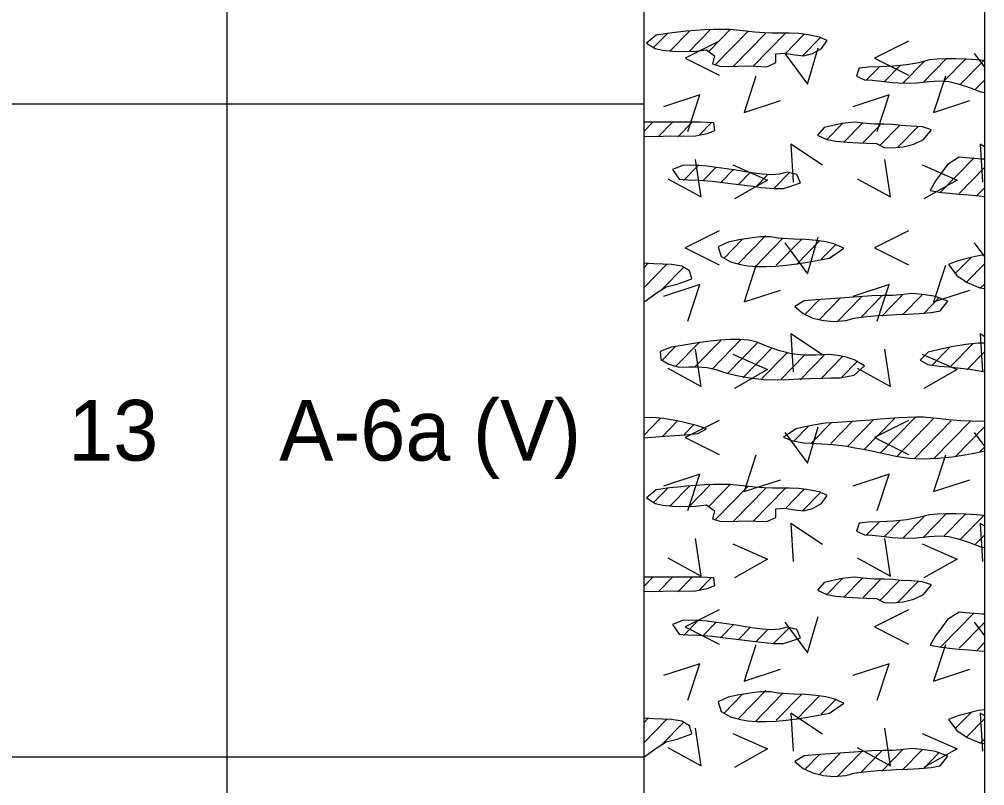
# Model space of a CAD drawing. Extents: x 0 to 0.83, y -0.65 to 1.27.
# Drawn here: x 0.7272 to 0.8333, y 0.5708 to 0.655 of the extents above; entities that cross this region are included whole.
import ezdxf

# ---------------------------------------------------------------- set-up
doc = ezdxf.new("R2010")
doc.units = 0

msp = doc.modelspace()

# ---------------------------------------------------------------- linework, layer by layer
for points in [[(0, 0), (0.83333, 0), (0.83333, 1.275), (0, 1.275)], [(0, 0), (0.83333, 0), (0.83333, 1.275), (0, 1.275)], [(0, 0), (0.83333, 0), (0.83333, 1.275), (0, 1.275)], [(0, 0), (0.83333, 0), (0.83333, 1.275), (0, 1.275)], [(0, 0), (0.83333, 0), (0.83333, 1.275), (0, 1.275)], [(0.79708, 0.65181), (0.79794, 0.65163), (0.79904, 0.65152), (0.80028, 0.65149), (0.80156, 0.65154), (0.80274, 0.65169), (0.80361, 0.65103), (0.80338, 0.65014), (0.80422, 0.64987), (0.80517, 0.64985), (0.80613, 0.6499), (0.8072, 0.64993), (0.80818, 0.6499), (0.80939, 0.64983), (0.81037, 0.65029), (0.81038, 0.65124), (0.8113, 0.6513), (0.81244, 0.65112), (0.81346, 0.65101), (0.81438, 0.65127), (0.81539, 0.65181), (0.81601, 0.65272), (0.81517, 0.65309), (0.81374, 0.65337), (0.81285, 0.65346), (0.81187, 0.65352), (0.81, 0.65352), (0.8091, 0.65354), (0.808, 0.65362), (0.80678, 0.65377), (0.8053, 0.6539), (0.80443, 0.65392), (0.80349, 0.6539), (0.80251, 0.65386), (0.80152, 0.6538), (0.80054, 0.65372), (0.79959, 0.65363), (0.7987, 0.65353), (0.79722, 0.65331), (0.79614, 0.65243)], [(0.83241, 0.65059), (0.83129, 0.65066), (0.83017, 0.65069), (0.8291, 0.65069), (0.82811, 0.65066), (0.82728, 0.65057), (0.82608, 0.65027), (0.82476, 0.65004), (0.8233, 0.6499), (0.82183, 0.64982), (0.82051, 0.64976), (0.81951, 0.64966), (0.81922, 0.6488), (0.82013, 0.64838), (0.82097, 0.64833), (0.822, 0.64823), (0.82318, 0.6481), (0.82448, 0.64801), (0.82584, 0.64804), (0.82719, 0.6482), (0.82836, 0.64827), (0.8294, 0.64819), (0.83043, 0.64795), (0.83156, 0.64756), (0.83291, 0.64707), (0.83333, 0.647), (0.83333, 0.65052)], [(0.79583, 0.64218), (0.79676, 0.64217), (0.79792, 0.64219), (0.79882, 0.64223), (0.79992, 0.64218), (0.80151, 0.64223), (0.80282, 0.64248), (0.80367, 0.6428), (0.80354, 0.64364), (0.80216, 0.64373), (0.79583, 0.64373)], [(0.81822, 0.64153), (0.81944, 0.64147), (0.82033, 0.64143), (0.82145, 0.64137), (0.82229, 0.64095), (0.82324, 0.64091), (0.82438, 0.64101), (0.82555, 0.6413), (0.82662, 0.64181), (0.82749, 0.6429), (0.82651, 0.64321), (0.82524, 0.64331), (0.82413, 0.64337), (0.82324, 0.64348), (0.82226, 0.6435), (0.82121, 0.64352), (0.81995, 0.64361), (0.81902, 0.64373), (0.81761, 0.64359), (0.81566, 0.64314), (0.81496, 0.6423), (0.81598, 0.64182), (0.81695, 0.64164)], [(0.83305, 0.63968), (0.83171, 0.63979), (0.83054, 0.63989), (0.82925, 0.63907), (0.82857, 0.63816), (0.82792, 0.63727), (0.82735, 0.63624), (0.82858, 0.63602), (0.82945, 0.63592), (0.83045, 0.63582), (0.83155, 0.63573), (0.83272, 0.63563), (0.83333, 0.63558), (0.83333, 0.63967)], [(0.80066, 0.63738), (0.80188, 0.63737), (0.80339, 0.63724), (0.80423, 0.63714), (0.8051, 0.63703), (0.806, 0.63692), (0.80692, 0.6368), (0.80784, 0.63668), (0.80875, 0.63657), (0.81014, 0.63643), (0.81119, 0.63644), (0.81222, 0.63678), (0.81308, 0.63707), (0.81267, 0.63797), (0.8116, 0.63822), (0.81075, 0.63802), (0.80989, 0.63794), (0.80885, 0.63802), (0.80799, 0.63813), (0.80703, 0.63827), (0.806, 0.63844), (0.80492, 0.6386), (0.80384, 0.63876), (0.8028, 0.63889), (0.80182, 0.63898), (0.8002, 0.63899), (0.79901, 0.63852), (0.79974, 0.63748)], [(0.81233, 0.63087), (0.81063, 0.63099), (0.80977, 0.63112), (0.8086, 0.63113), (0.80755, 0.63099), (0.80632, 0.63079), (0.80513, 0.63054), (0.80403, 0.63002), (0.80436, 0.62896), (0.80536, 0.62839), (0.80647, 0.6281), (0.8073, 0.62795), (0.80824, 0.62787), (0.80926, 0.62786), (0.81035, 0.62791), (0.81149, 0.62801), (0.81267, 0.62816), (0.81386, 0.62834), (0.81506, 0.62856), (0.81625, 0.62879), (0.81783, 0.62987), (0.81673, 0.63037), (0.81585, 0.63057), (0.8148, 0.63073), (0.81361, 0.63083)], [(0.83265, 0.62906), (0.83136, 0.62875), (0.83028, 0.62847), (0.82934, 0.62808), (0.83026, 0.62688), (0.83142, 0.62612), (0.83279, 0.62554), (0.83333, 0.62544), (0.83333, 0.62915)], [(0.79583, 0.62396), (0.79719, 0.62495), (0.79831, 0.62565), (0.79951, 0.62592), (0.80111, 0.62653), (0.80086, 0.62741), (0.80002, 0.62789), (0.79889, 0.62808), (0.79791, 0.62811), (0.79694, 0.62817), (0.79583, 0.62825)], [(0.82537, 0.6249), (0.82408, 0.62475), (0.82319, 0.6247), (0.82214, 0.62467), (0.82091, 0.62464), (0.81947, 0.62454), (0.81792, 0.62442), (0.81632, 0.6243), (0.81475, 0.62421), (0.81348, 0.62411), (0.81247, 0.62347), (0.81337, 0.62271), (0.81444, 0.62221), (0.81561, 0.62192), (0.81675, 0.62181), (0.81807, 0.62192), (0.81896, 0.6222), (0.82003, 0.62234), (0.82157, 0.62247), (0.82253, 0.62252), (0.82362, 0.62258), (0.82483, 0.62264), (0.82618, 0.62271), (0.82745, 0.62282), (0.82842, 0.62299), (0.82927, 0.62405), (0.82791, 0.62457), (0.82679, 0.62477)], [(0.79885, 0.619), (0.79763, 0.61854), (0.79773, 0.61764), (0.79859, 0.61712), (0.7997, 0.61682), (0.80074, 0.61683), (0.80165, 0.61684), (0.80281, 0.61676), (0.80377, 0.61655), (0.80486, 0.6162), (0.80606, 0.61591), (0.80751, 0.61563), (0.80905, 0.61545), (0.81052, 0.61542), (0.81177, 0.61547), (0.81289, 0.61551), (0.81408, 0.61555), (0.81553, 0.61559), (0.81642, 0.61562), (0.81745, 0.61565), (0.81897, 0.61592), (0.82011, 0.61696), (0.81896, 0.61763), (0.8181, 0.61789), (0.81717, 0.61809), (0.81626, 0.61819), (0.81479, 0.61814), (0.81343, 0.61814), (0.8121, 0.61829), (0.8108, 0.61859), (0.80953, 0.61905), (0.8082, 0.6196), (0.80736, 0.61976), (0.8064, 0.61984), (0.80536, 0.61984), (0.80427, 0.61978), (0.80314, 0.61967), (0.80201, 0.61952), (0.8009, 0.61935), (0.79984, 0.61917)], [(0.83263, 0.61944), (0.83126, 0.6193), (0.82969, 0.61904), (0.82883, 0.61887), (0.82712, 0.61846), (0.82623, 0.61759), (0.82708, 0.61709), (0.82831, 0.61691), (0.82941, 0.61684), (0.83033, 0.61675), (0.83165, 0.61657), (0.83253, 0.61643), (0.83333, 0.61629), (0.83333, 0.61943)], [(0.79583, 0.60904), (0.79715, 0.60915), (0.79814, 0.60922), (0.79922, 0.6093), (0.80039, 0.60938), (0.80179, 0.60951), (0.80275, 0.61002), (0.80179, 0.61036), (0.80091, 0.61058), (0.80003, 0.6108), (0.79909, 0.611), (0.79803, 0.61117), (0.79677, 0.61127), (0.79583, 0.61124)], [(0.82816, 0.60679), (0.82978, 0.60696), (0.83137, 0.60721), (0.8329, 0.60752), (0.83333, 0.60763), (0.83333, 0.61087), (0.83295, 0.61084), (0.83188, 0.61086), (0.83071, 0.61091), (0.82938, 0.61101), (0.82807, 0.61118), (0.82662, 0.6113), (0.82576, 0.6113), (0.82484, 0.61128), (0.82387, 0.61123), (0.82286, 0.61116), (0.82182, 0.61108), (0.82077, 0.61099), (0.81973, 0.61091), (0.81872, 0.61084), (0.81715, 0.61074), (0.81579, 0.61065), (0.81491, 0.61051), (0.81357, 0.61024), (0.8126, 0.61003), (0.81121, 0.60911), (0.8121, 0.60875), (0.81345, 0.6085), (0.81479, 0.60841), (0.81668, 0.60831), (0.81818, 0.60811), (0.81905, 0.60796), (0.82, 0.60778), (0.82107, 0.60757), (0.82225, 0.60732), (0.82357, 0.60703), (0.82501, 0.6068), (0.82656, 0.60673)], [(0.79708, 0.60181), (0.79794, 0.60163), (0.79904, 0.60152), (0.80028, 0.60149), (0.80156, 0.60154), (0.80274, 0.60169), (0.80361, 0.60103), (0.80338, 0.60014), (0.80422, 0.59987), (0.80517, 0.59985), (0.80613, 0.5999), (0.8072, 0.59993), (0.80818, 0.5999), (0.80939, 0.59983), (0.81037, 0.60029), (0.81038, 0.60124), (0.8113, 0.6013), (0.81244, 0.60112), (0.81346, 0.60101), (0.81438, 0.60127), (0.81539, 0.60181), (0.81601, 0.60272), (0.81517, 0.60309), (0.81374, 0.60337), (0.81285, 0.60346), (0.81187, 0.60352), (0.81, 0.60352), (0.8091, 0.60354), (0.808, 0.60362), (0.80678, 0.60377), (0.8053, 0.6039), (0.80443, 0.60392), (0.80349, 0.6039), (0.80251, 0.60386), (0.80152, 0.6038), (0.80054, 0.60372), (0.79959, 0.60363), (0.7987, 0.60353), (0.79722, 0.60331), (0.79614, 0.60243)], [(0.83241, 0.60059), (0.83129, 0.60066), (0.83017, 0.60069), (0.8291, 0.60069), (0.82811, 0.60066), (0.82728, 0.60057), (0.82608, 0.60027), (0.82476, 0.60004), (0.8233, 0.5999), (0.82183, 0.59982), (0.82051, 0.59976), (0.81951, 0.59966), (0.81922, 0.5988), (0.82013, 0.59838), (0.82097, 0.59833), (0.822, 0.59823), (0.82318, 0.5981), (0.82448, 0.59801), (0.82584, 0.59804), (0.82719, 0.5982), (0.82836, 0.59827), (0.8294, 0.59819), (0.83043, 0.59795), (0.83156, 0.59756), (0.83291, 0.59707), (0.83333, 0.597), (0.83333, 0.60052)], [(0.79583, 0.59218), (0.79676, 0.59217), (0.79792, 0.59219), (0.79882, 0.59223), (0.79992, 0.59218), (0.80151, 0.59223), (0.80282, 0.59248), (0.80367, 0.5928), (0.80354, 0.59364), (0.80216, 0.59373), (0.79583, 0.59373)], [(0.81822, 0.59153), (0.81944, 0.59147), (0.82033, 0.59143), (0.82145, 0.59137), (0.82229, 0.59095), (0.82324, 0.59091), (0.82438, 0.59101), (0.82555, 0.5913), (0.82662, 0.59181), (0.82749, 0.5929), (0.82651, 0.59321), (0.82524, 0.59331), (0.82413, 0.59337), (0.82324, 0.59348), (0.82226, 0.5935), (0.82121, 0.59352), (0.81995, 0.59361), (0.81902, 0.59373), (0.81761, 0.59359), (0.81566, 0.59314), (0.81496, 0.59231), (0.81598, 0.59182), (0.81695, 0.59164)], [(0.83305, 0.58968), (0.83171, 0.58979), (0.83054, 0.58989), (0.82925, 0.58907), (0.82857, 0.58816), (0.82792, 0.58727), (0.82735, 0.58624), (0.82858, 0.58602), (0.82945, 0.58592), (0.83045, 0.58582), (0.83155, 0.58573), (0.83272, 0.58563), (0.83333, 0.58558), (0.83333, 0.58967)], [(0.80066, 0.58738), (0.80188, 0.58737), (0.80339, 0.58724), (0.80423, 0.58714), (0.8051, 0.58703), (0.806, 0.58692), (0.80692, 0.5868), (0.80784, 0.58668), (0.80875, 0.58657), (0.81014, 0.58643), (0.81119, 0.58644), (0.81222, 0.58678), (0.81308, 0.58707), (0.81267, 0.58797), (0.8116, 0.58822), (0.81075, 0.58802), (0.80989, 0.58794), (0.80885, 0.58802), (0.80799, 0.58813), (0.80703, 0.58827), (0.806, 0.58844), (0.80492, 0.5886), (0.80384, 0.58876), (0.8028, 0.58889), (0.80182, 0.58898), (0.8002, 0.58899), (0.79901, 0.58852), (0.79974, 0.58748)], [(0.81233, 0.58087), (0.81063, 0.58099), (0.80977, 0.58112), (0.8086, 0.58113), (0.80755, 0.58099), (0.80632, 0.58079), (0.80513, 0.58054), (0.80403, 0.58002), (0.80436, 0.57896), (0.80536, 0.57839), (0.80647, 0.5781), (0.8073, 0.57795), (0.80824, 0.57787), (0.80926, 0.57786), (0.81035, 0.57791), (0.81149, 0.57801), (0.81267, 0.57816), (0.81386, 0.57834), (0.81506, 0.57856), (0.81625, 0.57879), (0.81783, 0.57987), (0.81673, 0.58037), (0.81585, 0.58057), (0.8148, 0.58073), (0.81361, 0.58083)], [(0.83265, 0.57906), (0.83136, 0.57875), (0.83028, 0.57847), (0.82934, 0.57808), (0.83026, 0.57688), (0.83142, 0.57612), (0.83279, 0.57554), (0.83333, 0.57544), (0.83333, 0.57915)], [(0.79583, 0.57396), (0.79719, 0.57495), (0.79831, 0.57565), (0.79951, 0.57592), (0.80111, 0.57653), (0.80086, 0.57741), (0.80002, 0.57789), (0.79889, 0.57808), (0.79791, 0.57811), (0.79694, 0.57817), (0.79583, 0.57825)], [(0.82537, 0.5749), (0.82408, 0.57476), (0.82319, 0.5747), (0.82214, 0.57467), (0.82091, 0.57464), (0.81947, 0.57454), (0.81792, 0.57442), (0.81632, 0.5743), (0.81475, 0.57421), (0.81348, 0.57411), (0.81247, 0.57347), (0.81337, 0.57271), (0.81444, 0.57221), (0.81561, 0.57192), (0.81675, 0.57181), (0.81807, 0.57192), (0.81896, 0.5722), (0.82003, 0.57234), (0.82157, 0.57247), (0.82253, 0.57252), (0.82362, 0.57258), (0.82483, 0.57264), (0.82618, 0.57271), (0.82745, 0.57282), (0.82842, 0.57299), (0.82927, 0.57405), (0.82791, 0.57457), (0.82679, 0.57477)]]:
    msp.add_lwpolyline(points, close=True)
for points in [[(0.75, 1.22083), (0.75, -0.64575)], [(0.75, 1.22083), (0.75, -0.64575)], [(0.79583, 1.22083), (0.79583, -0.64575)], [(0.83333, -0.64575), (0.83333, 1.13365)], [(0.79844, 0.65349), (0.79691, 0.65192)], [(0.79871, 0.65155), (0.80085, 0.65374)], [(0.80083, 0.65151), (0.80311, 0.65385)], [(0.80534, 0.65392), (0.80299, 0.65151)], [(0.80367, 0.65), (0.80732, 0.65374)], [(0.80571, 0.64988), (0.80924, 0.65349)], [(0.81142, 0.65351), (0.80785, 0.64986)], [(0.81141, 0.65129), (0.81348, 0.65341)], [(0.81528, 0.65304), (0.81331, 0.65103)], [(0.80412, 0.65263), (0.80038, 0.65076), (0.80412, 0.64888)], [(0.81134, 0.65129), (0.81384, 0.64791), (0.81503, 0.65191)], [(0.82496, 0.65263), (0.82121, 0.65076), (0.82496, 0.64888)], [(0.83217, 0.65129), (0.83333, 0.64973)], [(0.82035, 0.64837), (0.82176, 0.64982)], [(0.82233, 0.64819), (0.82408, 0.64998)], [(0.82433, 0.64802), (0.82666, 0.65041)], [(0.82909, 0.65069), (0.82656, 0.6481)], [(0.82885, 0.64823), (0.83122, 0.65066)], [(0.83325, 0.65052), (0.83065, 0.64786)], [(0.80818, 0.6488), (0.80687, 0.6448), (0.81087, 0.64611)], [(0.82901, 0.6488), (0.8277, 0.6448), (0.8317, 0.64611)], [(0.83333, 0.6484), (0.83227, 0.64731)], [(0.80069, 0.64272), (0.802, 0.64672), (0.798, 0.64541)], [(0.82152, 0.64272), (0.82284, 0.64672), (0.81884, 0.64541)], [(0.725, 0.64575), (0.75, 0.64575)], [(0.75, 0.64575), (0.79583, 0.64575)], [(0.79583, 0.6427), (0.79681, 0.6437)], [(0.79898, 0.64371), (0.79747, 0.64217)], [(0.80116, 0.64373), (0.79959, 0.64212)], [(0.80328, 0.64369), (0.80188, 0.64226)], [(0.8177, 0.64359), (0.81596, 0.64181)], [(0.81988, 0.64361), (0.81785, 0.64153)], [(0.82185, 0.64342), (0.81997, 0.64149)], [(0.824, 0.64341), (0.82178, 0.64113)], [(0.82601, 0.64325), (0.82378, 0.64097)], [(0.81551, 0.63899), (0.81201, 0.6413), (0.81226, 0.63712)], [(0.83333, 0.64098), (0.83284, 0.6413), (0.83309, 0.63712)], [(0.79847, 0.63751), (0.80215, 0.63551), (0.80153, 0.63963)], [(0.8193, 0.63751), (0.82299, 0.63551), (0.82236, 0.63963)], [(0.83217, 0.6398), (0.82844, 0.63599)], [(0.80188, 0.63903), (0.8002, 0.63731)], [(0.8038, 0.63879), (0.80237, 0.63732)], [(0.80575, 0.63857), (0.80429, 0.63708)], [(0.80562, 0.63905), (0.80946, 0.63737), (0.80581, 0.63531)], [(0.80758, 0.63824), (0.80627, 0.63689)], [(0.81188, 0.63821), (0.81016, 0.63646)], [(0.82645, 0.63905), (0.83029, 0.63737), (0.82664, 0.63531)], [(0.83333, 0.63879), (0.83052, 0.63591)], [(0.80941, 0.6379), (0.80816, 0.63662)], [(0.83333, 0.63657), (0.83245, 0.63567)], [(0.80412, 0.6318), (0.80038, 0.62992), (0.80412, 0.62805)], [(0.82496, 0.6318), (0.82121, 0.62992), (0.82496, 0.62805)], [(0.80465, 0.62875), (0.80667, 0.63083)], [(0.80626, 0.62819), (0.80928, 0.63128)], [(0.80809, 0.62785), (0.81111, 0.63095)], [(0.81041, 0.62802), (0.81318, 0.63085)], [(0.81134, 0.63046), (0.81384, 0.62708), (0.81503, 0.63108)], [(0.81264, 0.62809), (0.81518, 0.63069)], [(0.81536, 0.62867), (0.81699, 0.63033)], [(0.83217, 0.63046), (0.83333, 0.62889)], [(0.8301, 0.62709), (0.83184, 0.62887)], [(0.7963, 0.62821), (0.79583, 0.62772)], [(0.79834, 0.62808), (0.79583, 0.62551)], [(0.79786, 0.62538), (0.80023, 0.6278)], [(0.80818, 0.62797), (0.80687, 0.62397), (0.81087, 0.62528)], [(0.82901, 0.62797), (0.8277, 0.62397), (0.8317, 0.62528)], [(0.83131, 0.62612), (0.83333, 0.62819)], [(0.80069, 0.62188), (0.802, 0.62588), (0.798, 0.62457)], [(0.82152, 0.62188), (0.82284, 0.62588), (0.81884, 0.62457)], [(0.83285, 0.62549), (0.83333, 0.62598)], [(0.81519, 0.62428), (0.81354, 0.62258)], [(0.81514, 0.62201), (0.81748, 0.62441)], [(0.81709, 0.6218), (0.81974, 0.62451)], [(0.8197, 0.62225), (0.82203, 0.62465)], [(0.82202, 0.62241), (0.8243, 0.62475)], [(0.82431, 0.62255), (0.82644, 0.62474)], [(0.82663, 0.62271), (0.82834, 0.62447)], [(0.81551, 0.61816), (0.81201, 0.62047), (0.81226, 0.61628)], [(0.83333, 0.62015), (0.83284, 0.62047), (0.83309, 0.61628)], [(0.79938, 0.61913), (0.79786, 0.61758)], [(0.79933, 0.61687), (0.80195, 0.61956)], [(0.80142, 0.6168), (0.8043, 0.61975)], [(0.80653, 0.61983), (0.8034, 0.61661)], [(0.80506, 0.6161), (0.8084, 0.61952)], [(0.82751, 0.61698), (0.82945, 0.61896)], [(0.83203, 0.61939), (0.82949, 0.61679)], [(0.79847, 0.61668), (0.80215, 0.61468), (0.80153, 0.6188)], [(0.80562, 0.61822), (0.80946, 0.61654), (0.80581, 0.61448)], [(0.80997, 0.61893), (0.80675, 0.61562)], [(0.81164, 0.61842), (0.80884, 0.61555)], [(0.81353, 0.61814), (0.81094, 0.61549)], [(0.81303, 0.61542), (0.81579, 0.61825)], [(0.81534, 0.61558), (0.81768, 0.61797)], [(0.8193, 0.61668), (0.82299, 0.61468), (0.82236, 0.6188)], [(0.82645, 0.61822), (0.83029, 0.61654), (0.82664, 0.61448)], [(0.83138, 0.61652), (0.83333, 0.61852)], [(0.8176, 0.61568), (0.81934, 0.61747)], [(0.83333, 0.6163), (0.83333, 0.6163)], [(0.79765, 0.61115), (0.79583, 0.60928)], [(0.7996, 0.61094), (0.79786, 0.60915)], [(0.80412, 0.61096), (0.80038, 0.60909), (0.80412, 0.60721)], [(0.8143, 0.60848), (0.8165, 0.61073)], [(0.8164, 0.60841), (0.81879, 0.61086)], [(0.81829, 0.60813), (0.82114, 0.61105)], [(0.82004, 0.60771), (0.82346, 0.61122)], [(0.82496, 0.61096), (0.82121, 0.60909), (0.82496, 0.60721)], [(0.82569, 0.61129), (0.82184, 0.60735)], [(0.82775, 0.61119), (0.8237, 0.60704)], [(0.82964, 0.61092), (0.82557, 0.60674)], [(0.83173, 0.61085), (0.82774, 0.60676)], [(0.8013, 0.61046), (0.80027, 0.60941)], [(0.81134, 0.60962), (0.81384, 0.60625), (0.81503, 0.61025)], [(0.81392, 0.6103), (0.81235, 0.60869)], [(0.83333, 0.61027), (0.83012, 0.60698)], [(0.83217, 0.60962), (0.83333, 0.60806)], [(0.83281, 0.60752), (0.83333, 0.60806)], [(0.80818, 0.60713), (0.80687, 0.60313), (0.81087, 0.60444)], [(0.82901, 0.60713), (0.8277, 0.60313), (0.8317, 0.60444)], [(0.80069, 0.60105), (0.802, 0.60505), (0.798, 0.60374)], [(0.82152, 0.60105), (0.82284, 0.60505), (0.81884, 0.60374)], [(0.79844, 0.60349), (0.79691, 0.60192)], [(0.79871, 0.60155), (0.80085, 0.60374)], [(0.80083, 0.60151), (0.80311, 0.60385)], [(0.80534, 0.60392), (0.80299, 0.60151)], [(0.80367, 0.6), (0.80732, 0.60374)], [(0.80571, 0.59988), (0.80924, 0.60349)], [(0.81142, 0.60351), (0.80785, 0.59986)], [(0.81141, 0.60129), (0.81348, 0.60341)], [(0.81528, 0.60304), (0.81331, 0.60103)], [(0.82233, 0.59819), (0.82408, 0.59998)], [(0.82433, 0.59802), (0.82666, 0.60041)], [(0.82909, 0.60069), (0.82656, 0.5981)], [(0.82885, 0.59823), (0.83122, 0.60066)], [(0.83325, 0.60052), (0.83065, 0.59786)], [(0.81551, 0.59733), (0.81201, 0.59964), (0.81226, 0.59545)], [(0.82035, 0.59837), (0.82176, 0.59982)], [(0.83333, 0.59932), (0.83284, 0.59964), (0.83309, 0.59545)], [(0.79847, 0.59584), (0.80215, 0.59384), (0.80153, 0.59797)], [(0.8193, 0.59584), (0.82299, 0.59384), (0.82236, 0.59797)], [(0.83333, 0.5984), (0.83227, 0.59731)], [(0.80562, 0.59739), (0.80946, 0.5957), (0.80581, 0.59364)], [(0.82645, 0.59739), (0.83029, 0.5957), (0.82664, 0.59364)], [(0.79583, 0.5927), (0.79681, 0.5937)], [(0.79898, 0.59371), (0.79747, 0.59217)], [(0.80116, 0.59373), (0.79959, 0.59213)], [(0.80328, 0.59369), (0.80188, 0.59226)], [(0.8177, 0.59359), (0.81596, 0.59181)], [(0.81988, 0.59361), (0.81785, 0.59153)], [(0.82185, 0.59342), (0.81997, 0.59149)], [(0.824, 0.59341), (0.82178, 0.59113)], [(0.82601, 0.59325), (0.82378, 0.59097)], [(0.80412, 0.59013), (0.80038, 0.58826), (0.80412, 0.58638)], [(0.81134, 0.58879), (0.81384, 0.58541), (0.81503, 0.58941)], [(0.82496, 0.59013), (0.82121, 0.58826), (0.82496, 0.58638)], [(0.83217, 0.5898), (0.82844, 0.58599)], [(0.80188, 0.58903), (0.8002, 0.58731)], [(0.8038, 0.58879), (0.80237, 0.58732)], [(0.80575, 0.58857), (0.80429, 0.58708)], [(0.80758, 0.58824), (0.80627, 0.58689)], [(0.81188, 0.58821), (0.81016, 0.58646)], [(0.83333, 0.58879), (0.83052, 0.58591)], [(0.83217, 0.58879), (0.83333, 0.58723)], [(0.80941, 0.5879), (0.80816, 0.58662)], [(0.80818, 0.5863), (0.80687, 0.5823), (0.81087, 0.58361)], [(0.82901, 0.5863), (0.8277, 0.5823), (0.8317, 0.58361)], [(0.83333, 0.58657), (0.83245, 0.58567)], [(0.80069, 0.58022), (0.802, 0.58422), (0.798, 0.58291)], [(0.82152, 0.58022), (0.82284, 0.58422), (0.81884, 0.58291)], [(0.80465, 0.57875), (0.80667, 0.58083)], [(0.80626, 0.57819), (0.80928, 0.58128)], [(0.80809, 0.57785), (0.81111, 0.58095)], [(0.81041, 0.57802), (0.81318, 0.58085)], [(0.81264, 0.57809), (0.81518, 0.58069)], [(0.81536, 0.57867), (0.81699, 0.58033)], [(0.81551, 0.57649), (0.81201, 0.5788), (0.81226, 0.57462)], [(0.8301, 0.57709), (0.83184, 0.57887)], [(0.83333, 0.57848), (0.83284, 0.5788), (0.83309, 0.57462)], [(0.7963, 0.57821), (0.79583, 0.57772)], [(0.79834, 0.57808), (0.79583, 0.57551)], [(0.79786, 0.57538), (0.80023, 0.5778)], [(0.83131, 0.57612), (0.83333, 0.57819)], [(0.79847, 0.57501), (0.80215, 0.57301), (0.80153, 0.57713)], [(0.80562, 0.57655), (0.80946, 0.57487), (0.80581, 0.57281)], [(0.8193, 0.57501), (0.82299, 0.57301), (0.82236, 0.57713)], [(0.82645, 0.57655), (0.83029, 0.57487), (0.82664, 0.57281)], [(0.83285, 0.57549), (0.83333, 0.57598)], [(0.81514, 0.57201), (0.81748, 0.57441)], [(0.81709, 0.5718), (0.81974, 0.57451)], [(0.8197, 0.57225), (0.82203, 0.57465)], [(0.82202, 0.57241), (0.8243, 0.57475)], [(0.82431, 0.57255), (0.82644, 0.57474)], [(0.82663, 0.57271), (0.82834, 0.57447)], [(0.725, 0.574), (0.75, 0.574)], [(0.75, 0.574), (0.79583, 0.574)], [(0.81519, 0.57428), (0.81354, 0.57258)]]:
    msp.add_lwpolyline(points)

# ---------------------------------------------------------------- texts
for s, p in [('13', (0.73253, 0.60654)), ('A-6a (V)', (0.75575, 0.60654))]:
    msp.add_text(s, height=0.006667).set_placement(p)

doc.saveas('drawing.dxf')
